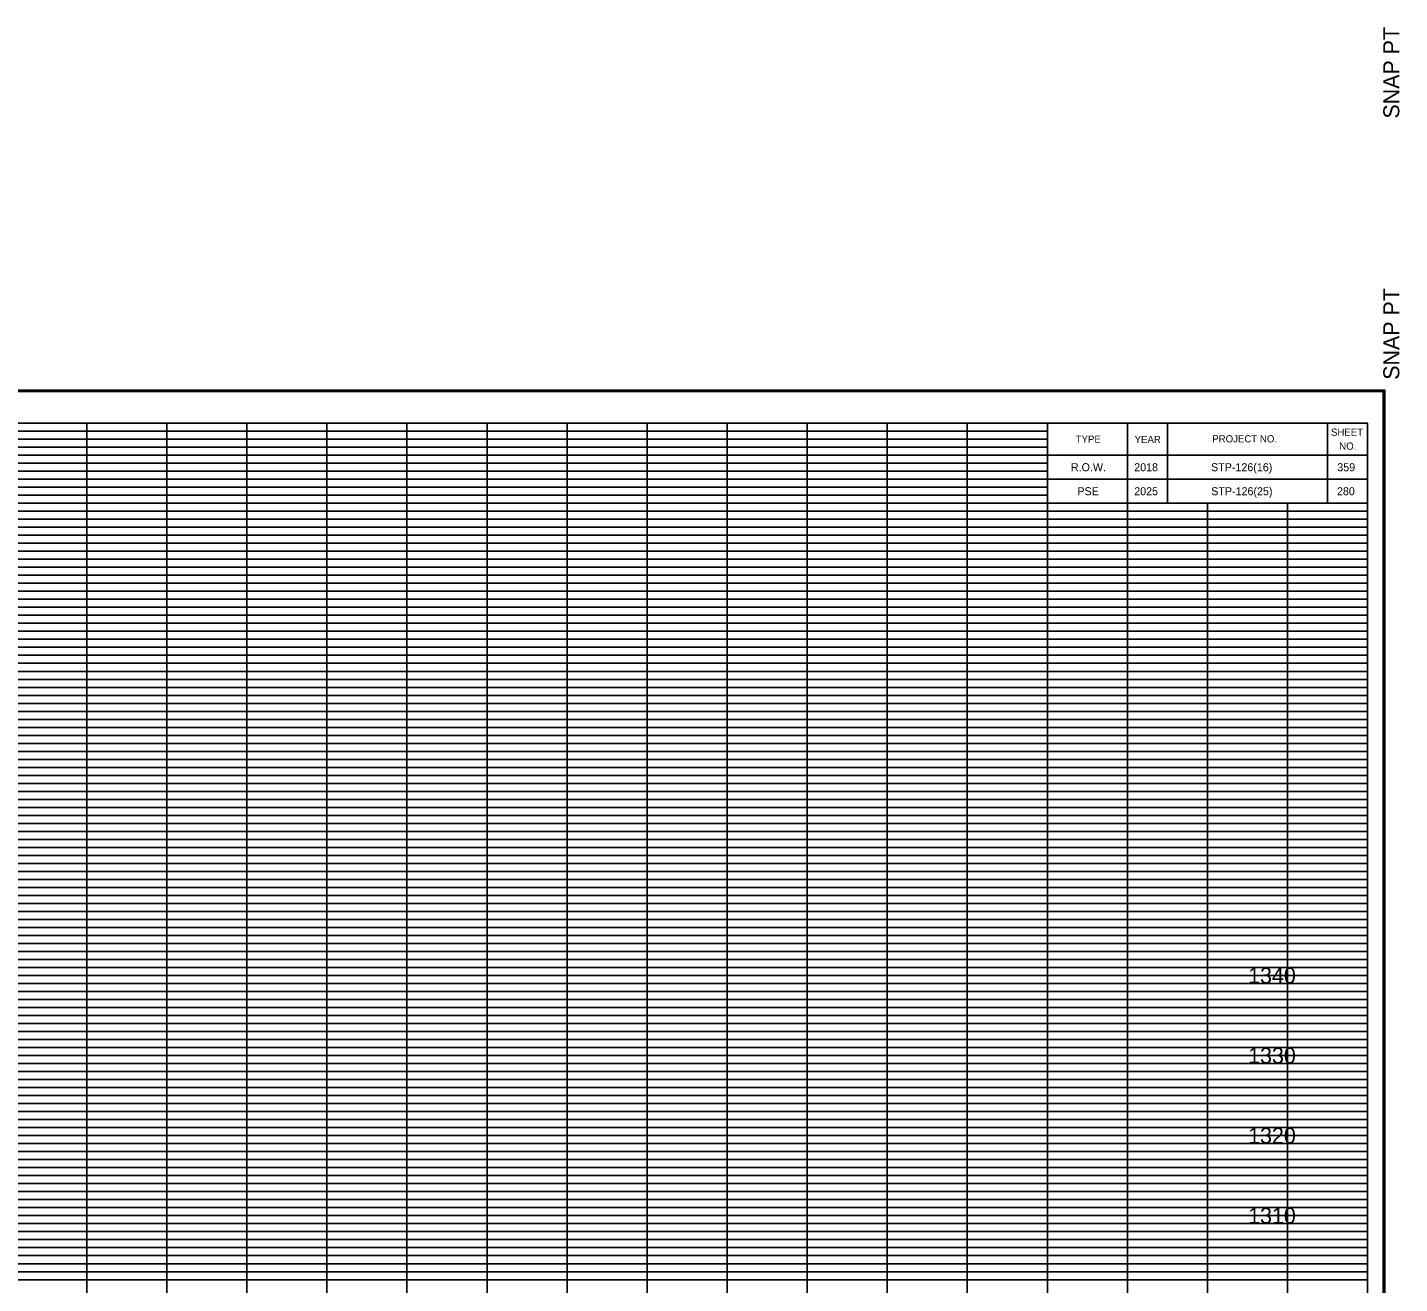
# Model space of a CAD drawing. Extents: x 980 to 1324, y 978 to 2847.
# Drawn here: x 1152.6 to 1324, y 1642.5 to 1799.4 of the extents above; entities that cross this region are included whole.
import ezdxf

# ---------------------------------------------------------------- set-up
doc = ezdxf.new("R2010")
doc.units = 0
for name, color, linetype in [('DESIGN - SCRATCH - User 1', 7, 'Continuous'), ('DESIGN - SHEET - Corner Text', 7, 'Continuous'), ('DESIGN - SHEET - Light Grid', 7, 'Continuous'), ('DESIGN - SHEET - Linework', 7, 'Continuous'), ('DESIGN - SHEET - Plot Shape', 7, 'Continuous'), ('DESIGN - TYPICAL - Text', 7, 'Continuous')]:
    doc.layers.add(name, color=color, linetype=linetype)

# ---------------------------------------------------------------- blocks, each defined once
blk = doc.blocks.new('XSTSHT')
at = {"layer": 'DESIGN - SCRATCH - User 1'}
for p, q in [((28.5, 20.45), (28.5, 20.45)), ((29.24, 20.45), (29.24, 20.45)), ((30.49, 20.45), (30.49, 20.45)), ((31.74, 20.45), (31.74, 20.45)), ((28.5, 20.15), (28.5, 20.15)), ((29.24, 20.15), (29.24, 20.15)), ((30.49, 20.15), (30.49, 20.15)), ((31.74, 20.15), (31.74, 20.15))]:
    blk.add_line(p, q, dxfattribs=at)
at = {"layer": 'DESIGN - SHEET - Light Grid'}
for p, q in [((8, 20.9), (16, 20.9)), ((8, 20.8), (16, 20.8)), ((16, 20.9), (24, 20.9)), ((16, 20.8), (24, 20.8)), ((24, 20.9), (28, 20.9)), ((24, 20.8), (28, 20.8)), ((8, 20.7), (16, 20.7)), ((8, 20.6), (16, 20.6)), ((16, 20.7), (24, 20.7)), ((16, 20.6), (24, 20.6)), ((24, 20.7), (28, 20.7)), ((24, 20.6), (28, 20.6)), ((8, 20.5), (16, 20.5)), ((8, 20.4), (16, 20.4)), ((16, 20.5), (24, 20.5)), ((16, 20.4), (24, 20.4)), ((24, 20.5), (28, 20.5)), ((24, 20.4), (28, 20.4)), ((8, 20.3), (16, 20.3)), ((16, 20.3), (24, 20.3)), ((24, 20.3), (28, 20.3)), ((8, 20.2), (16, 20.2)), ((8, 20.1), (16, 20.1)), ((16, 20.2), (24, 20.2)), ((16, 20.1), (24, 20.1)), ((24, 20.2), (28, 20.2)), ((24, 20.1), (28, 20.1)), ((8, 19.9), (16, 19.9)), ((16, 19.9), (24, 19.9)), ((24, 19.9), (32, 19.9)), ((8, 19.8), (16, 19.8)), ((16, 19.8), (24, 19.8)), ((24, 19.8), (32, 19.8)), ((8, 19.7), (16, 19.7)), ((8, 19.6), (16, 19.6)), ((16, 19.7), (24, 19.7)), ((16, 19.6), (24, 19.6)), ((24, 19.7), (32, 19.7)), ((24, 19.6), (32, 19.6)), ((8, 19.5), (16, 19.5)), ((8, 19.4), (16, 19.4)), ((16, 19.5), (24, 19.5)), ((16, 19.4), (24, 19.4)), ((24, 19.5), (32, 19.5)), ((24, 19.4), (32, 19.4)), ((8, 19.3), (16, 19.3)), ((8, 19.2), (16, 19.2)), ((16, 19.3), (24, 19.3)), ((16, 19.2), (24, 19.2)), ((24, 19.3), (32, 19.3)), ((24, 19.2), (32, 19.2)), ((8, 19.1), (16, 19.1)), ((16, 19.1), (24, 19.1)), ((24, 19.1), (32, 19.1)), ((8, 18.9), (16, 18.9)), ((16, 18.9), (24, 18.9)), ((24, 18.9), (32, 18.9)), ((8, 18.8), (16, 18.8)), ((8, 18.7), (16, 18.7)), ((16, 18.8), (24, 18.8)), ((16, 18.7), (24, 18.7)), ((24, 18.8), (32, 18.8)), ((24, 18.7), (32, 18.7)), ((8, 18.6), (16, 18.6)), ((16, 18.6), (24, 18.6)), ((24, 18.6), (32, 18.6)), ((8, 18.5), (16, 18.5)), ((8, 18.4), (16, 18.4)), ((16, 18.5), (24, 18.5)), ((16, 18.4), (24, 18.4)), ((24, 18.5), (32, 18.5)), ((24, 18.4), (32, 18.4)), ((8, 18.3), (16, 18.3)), ((8, 18.2), (16, 18.2)), ((16, 18.3), (24, 18.3)), ((16, 18.2), (24, 18.2)), ((24, 18.3), (32, 18.3)), ((24, 18.2), (32, 18.2)), ((8, 18.1), (16, 18.1)), ((16, 18.1), (24, 18.1)), ((24, 18.1), (32, 18.1)), ((8, 17.9), (16, 17.9)), ((16, 17.9), (24, 17.9)), ((24, 17.9), (32, 17.9)), ((8, 17.8), (16, 17.8)), ((8, 17.7), (16, 17.7)), ((16, 17.8), (24, 17.8)), ((16, 17.7), (24, 17.7)), ((24, 17.8), (32, 17.8)), ((24, 17.7), (32, 17.7)), ((8, 17.6), (16, 17.6)), ((8, 17.5), (16, 17.5)), ((16, 17.6), (24, 17.6)), ((16, 17.5), (24, 17.5)), ((24, 17.6), (32, 17.6)), ((24, 17.5), (32, 17.5)), ((8, 17.4), (16, 17.4)), ((16, 17.4), (24, 17.4)), ((24, 17.4), (32, 17.4)), ((8, 17.3), (16, 17.3)), ((8, 17.2), (16, 17.2)), ((16, 17.3), (24, 17.3)), ((16, 17.2), (24, 17.2)), ((24, 17.3), (32, 17.3)), ((24, 17.2), (32, 17.2)), ((8, 17.1), (16, 17.1)), ((16, 17.1), (24, 17.1)), ((24, 17.1), (32, 17.1)), ((8, 16.9), (16, 16.9)), ((8, 16.8), (16, 16.8)), ((16, 16.9), (24, 16.9)), ((16, 16.8), (24, 16.8)), ((24, 16.9), (32, 16.9)), ((24, 16.8), (32, 16.8)), ((8, 16.7), (16, 16.7)), ((16, 16.7), (24, 16.7)), ((24, 16.7), (32, 16.7)), ((8, 16.6), (16, 16.6)), ((8, 16.5), (16, 16.5)), ((16, 16.6), (24, 16.6)), ((16, 16.5), (24, 16.5)), ((24, 16.6), (32, 16.6)), ((24, 16.5), (32, 16.5)), ((8, 16.4), (16, 16.4)), ((8, 16.3), (16, 16.3)), ((16, 16.4), (24, 16.4)), ((16, 16.3), (24, 16.3)), ((24, 16.4), (32, 16.4)), ((24, 16.3), (32, 16.3)), ((8, 16.2), (16, 16.2)), ((16, 16.2), (24, 16.2)), ((24, 16.2), (32, 16.2)), ((8, 16.1), (16, 16.1)), ((16, 16.1), (24, 16.1)), ((24, 16.1), (32, 16.1)), ((8, 15.9), (16, 15.9)), ((8, 15.8), (16, 15.8)), ((16, 15.9), (24, 15.9)), ((16, 15.8), (24, 15.8)), ((24, 15.9), (32, 15.9)), ((24, 15.8), (32, 15.8)), ((8, 15.7), (16, 15.7)), ((8, 15.6), (16, 15.6)), ((16, 15.7), (24, 15.7)), ((16, 15.6), (24, 15.6)), ((24, 15.7), (32, 15.7)), ((24, 15.6), (32, 15.6)), ((8, 15.5), (16, 15.5)), ((16, 15.5), (24, 15.5)), ((24, 15.5), (32, 15.5)), ((8, 15.4), (16, 15.4)), ((8, 15.3), (16, 15.3)), ((16, 15.4), (24, 15.4)), ((16, 15.3), (24, 15.3)), ((24, 15.4), (32, 15.4)), ((24, 15.3), (32, 15.3)), ((8, 15.2), (16, 15.2)), ((8, 15.1), (16, 15.1)), ((16, 15.2), (24, 15.2)), ((16, 15.1), (24, 15.1)), ((24, 15.2), (32, 15.2)), ((24, 15.1), (32, 15.1)), ((8, 14.9), (16, 14.9)), ((8, 14.8), (16, 14.8)), ((16, 14.9), (24, 14.9)), ((16, 14.8), (24, 14.8)), ((24, 14.9), (32, 14.9)), ((24, 14.8), (32, 14.8)), ((8, 14.7), (16, 14.7)), ((8, 14.6), (16, 14.6)), ((16, 14.7), (24, 14.7)), ((16, 14.6), (24, 14.6)), ((24, 14.7), (32, 14.7)), ((24, 14.6), (32, 14.6)), ((8, 14.5), (16, 14.5)), ((8, 14.4), (16, 14.4)), ((16, 14.5), (24, 14.5)), ((16, 14.4), (24, 14.4)), ((24, 14.5), (32, 14.5)), ((24, 14.4), (32, 14.4)), ((8, 14.3), (16, 14.3)), ((16, 14.3), (24, 14.3)), ((24, 14.3), (32, 14.3)), ((8, 14.2), (16, 14.2)), ((8, 14.1), (16, 14.1)), ((16, 14.2), (24, 14.2)), ((16, 14.1), (24, 14.1)), ((24, 14.2), (32, 14.2)), ((24, 14.1), (32, 14.1)), ((8, 13.9), (16, 13.9)), ((16, 13.9), (24, 13.9)), ((24, 13.9), (32, 13.9)), ((8, 13.8), (16, 13.8)), ((16, 13.8), (24, 13.8)), ((24, 13.8), (32, 13.8)), ((8, 13.7), (16, 13.7)), ((8, 13.6), (16, 13.6)), ((16, 13.7), (24, 13.7)), ((16, 13.6), (24, 13.6)), ((24, 13.7), (32, 13.7)), ((24, 13.6), (32, 13.6)), ((8, 13.5), (16, 13.5)), ((8, 13.4), (16, 13.4)), ((16, 13.5), (24, 13.5)), ((16, 13.4), (24, 13.4)), ((24, 13.5), (32, 13.5)), ((24, 13.4), (32, 13.4)), ((8, 13.3), (16, 13.3)), ((8, 13.2), (16, 13.2)), ((16, 13.3), (24, 13.3)), ((16, 13.2), (24, 13.2)), ((24, 13.3), (32, 13.3)), ((24, 13.2), (32, 13.2)), ((8, 13.1), (16, 13.1)), ((16, 13.1), (24, 13.1)), ((24, 13.1), (32, 13.1)), ((8, 12.9), (16, 12.9)), ((16, 12.9), (24, 12.9)), ((24, 12.9), (32, 12.9)), ((8, 12.8), (16, 12.8)), ((8, 12.7), (16, 12.7)), ((16, 12.8), (24, 12.8)), ((16, 12.7), (24, 12.7)), ((24, 12.8), (32, 12.8)), ((24, 12.7), (32, 12.7)), ((8, 12.6), (16, 12.6)), ((16, 12.6), (24, 12.6)), ((24, 12.6), (32, 12.6)), ((8, 12.5), (16, 12.5)), ((8, 12.4), (16, 12.4)), ((16, 12.5), (24, 12.5)), ((16, 12.4), (24, 12.4)), ((24, 12.5), (32, 12.5)), ((24, 12.4), (32, 12.4)), ((8, 12.3), (16, 12.3)), ((8, 12.2), (16, 12.2)), ((16, 12.3), (24, 12.3)), ((16, 12.2), (24, 12.2)), ((24, 12.3), (32, 12.3)), ((24, 12.2), (32, 12.2)), ((8, 12.1), (16, 12.1)), ((16, 12.1), (24, 12.1)), ((24, 12.1), (32, 12.1)), ((8, 11.9), (16, 11.9)), ((16, 11.9), (24, 11.9)), ((24, 11.9), (32, 11.9)), ((8, 11.8), (16, 11.8)), ((8, 11.7), (16, 11.7)), ((16, 11.8), (24, 11.8)), ((16, 11.7), (24, 11.7)), ((24, 11.8), (32, 11.8)), ((24, 11.7), (32, 11.7)), ((8, 11.6), (16, 11.6)), ((8, 11.5), (16, 11.5)), ((16, 11.6), (24, 11.6)), ((16, 11.5), (24, 11.5)), ((24, 11.6), (32, 11.6)), ((24, 11.5), (32, 11.5)), ((8, 11.4), (16, 11.4)), ((16, 11.4), (24, 11.4)), ((24, 11.4), (32, 11.4)), ((8, 11.3), (16, 11.3)), ((8, 11.2), (16, 11.2)), ((16, 11.3), (24, 11.3)), ((16, 11.2), (24, 11.2)), ((24, 11.3), (32, 11.3)), ((24, 11.2), (32, 11.2)), ((8, 11.1), (16, 11.1)), ((16, 11.1), (24, 11.1)), ((24, 11.1), (32, 11.1)), ((8, 10.9), (16, 10.9)), ((8, 10.8), (16, 10.8)), ((16, 10.9), (24, 10.9)), ((16, 10.8), (24, 10.8)), ((24, 10.9), (32, 10.9)), ((24, 10.8), (32, 10.8)), ((8, 10.7), (16, 10.7)), ((16, 10.7), (24, 10.7)), ((24, 10.7), (32, 10.7)), ((8, 10.6), (16, 10.6)), ((8, 10.5), (16, 10.5)), ((16, 10.6), (24, 10.6)), ((16, 10.5), (24, 10.5)), ((24, 10.6), (32, 10.6)), ((24, 10.5), (32, 10.5)), ((8, 10.4), (16, 10.4)), ((8, 10.3), (16, 10.3)), ((16, 10.4), (24, 10.4)), ((16, 10.3), (24, 10.3)), ((24, 10.4), (32, 10.4)), ((24, 10.3), (32, 10.3))]:
    blk.add_line(p, q, dxfattribs=at)
at = {"layer": 'DESIGN - SHEET - Linework'}
for p, q in [((-1.823, 21.414), (32.217, 21.414)), ((32.217, 21.414), (32.217, -0.414)), ((16, 0), (16, 21)), ((17, 0), (17, 21)), ((18, 0), (18, 21)), ((19, 0), (19, 21)), ((20, 0), (20, 21)), ((21, 0), (21, 21)), ((22, 0), (22, 21)), ((23, 0), (23, 21)), ((24, 0), (24, 21)), ((25, 0), (25, 21)), ((26, 0), (26, 21)), ((27, 0), (27, 21)), ((0, 20), (28, 20)), ((28, 0), (28, 20)), ((29, 0), (29, 20)), ((30, 0), (30, 20)), ((31, 0), (31, 20)), ((0, 19), (32, 19)), ((0, 18), (32, 18)), ((0, 17), (32, 17)), ((0, 16), (32, 16)), ((0, 15), (32, 15)), ((0, 14), (32, 14)), ((0, 13), (32, 13)), ((0, 12), (32, 12)), ((0, 11), (32, 11))]:
    blk.add_line(p, q, dxfattribs=at)
for points in [[(0, 21), (0, 0), (32, 0), (32, 21), (0, 21)], [(28, 21), (28, 20), (32, 20), (32, 21), (31.5, 21), (31.5, 20), (29.5, 20), (29.5, 21), (29, 21), (29, 20), (32, 20), (28, 20), (28, 20.3), (32, 20.3), (32, 20.6), (28, 20.6)]]:
    blk.add_lwpolyline(points, dxfattribs=at)
at = {"layer": 'DESIGN - SHEET - Plot Shape'}
for points in [[(-1.803, 21.394), (32.197, 21.394), (32.197, -0.394), (-1.803, -0.394)], [(-0.85, 21), (32, 21), (32, -0.25), (-0.85, -0.25)]]:
    blk.add_lwpolyline(points, close=True, dxfattribs=at)
at = {"layer": 'DESIGN - SHEET - Corner Text'}
for s, p in [('  SNAP PT', (32.397, 21.394)), ('SNAP PT  ', (32.397, -2.194))]:
    blk.add_text(s, height=0.2, rotation=90, dxfattribs=at).set_placement(p)
for s, p in [('SHEET', (31.543, 20.843)), ('TYPE', (28.354, 20.756)), ('YEAR', (29.09, 20.752)), ('PROJECT NO.', (30.06, 20.76)), ('NO.', (31.646, 20.669))]:
    blk.add_text(s, height=0.09, dxfattribs=at).set_placement(p)

msp = doc.modelspace()

# ---------------------------------------------------------------- linework, layer by layer
at = {"layer": 'DESIGN - SHEET - Plot Shape'}
msp.add_lwpolyline([(991.5, 1537.5), (1320, 1537.5), (1320, 1750), (991.5, 1750)], close=True, dxfattribs=at)

# ---------------------------------------------------------------- block references
at = {"layer": 'DESIGN - SHEET - Plot Shape', "xscale": 10, "yscale": 10}
for p in [(1000, 1810), (1000, 1540)]:
    msp.add_blockref('XSTSHT', p, dxfattribs=at)

# ---------------------------------------------------------------- texts
at = {"layer": 'DESIGN - SHEET - Corner Text'}
for s, p in [('R.O.W.', (1282.94, 1744)), ('2018', (1290.85, 1744)), ('STP-126(16)', (1300.45, 1744)), ('359', (1316.22, 1744)), ('PSE', (1283.75, 1741)), ('2025', (1290.85, 1741)), ('STP-126(25)', (1300.47, 1741)), ('280', (1316.18, 1741))]:
    msp.add_text(s, height=1, dxfattribs=at).set_placement(p)
at = {"layer": 'DESIGN - TYPICAL - Text'}
for s, p in [('     1340     ', (1301.37, 1680)), ('     1330     ', (1301.37, 1670)), ('     1320     ', (1301.37, 1660)), ('     1310     ', (1301.37, 1650))]:
    msp.add_text(s, height=2, dxfattribs=at).set_placement(p)

doc.saveas('drawing.dxf')
